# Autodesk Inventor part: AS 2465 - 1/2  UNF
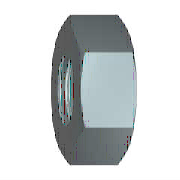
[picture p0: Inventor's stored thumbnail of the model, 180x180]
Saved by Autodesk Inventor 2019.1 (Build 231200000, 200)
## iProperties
IsCustomPart: 0
Created: 2018-01
Part Number: AS 2465 - 1/2  UNF
Material: Steel, Mild
Description: Unified hexagon bolts, screws and nuts (UNC and UNF threads)
Document SubType Name: Modeling
Standard: AS 2465
Designer: Justin
Standards Organization: AS
Language: en-US
Size Designation: 1/2  UNF
Categories: <MemberInstance><Categories><Category DisplayName="Fasteners" InternalName="e4da775c-781d-43d5-af7c-5136215cf5a6" Mnemonic="FSTN"><Category DisplayName="Nuts" I
Density: 7.85 g/cm^3
Appearance: Semi-Polished
Mass: 18.8733 g
Surface Area: 15.332 cm^2
Volume: 2.40424 cm^3
Author: Justin
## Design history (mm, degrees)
sketch "Sketch1"
  geometry: L1 (-10.999, 0)-(-5.499, 9.525); L2 (-5.499, 9.525)-(5.499, 9.525); L3 (5.499, 9.525)-(10.999, 0); L4 (10.999, 0)-(5.499, -9.525); L5 (5.499, -9.525)-(-5.499, -9.525); L6 (-5.499, -9.525)-(-10.999, 0); 2 further points
  constraints: 12 end point, 1 coincident, 1 horizontal, 11 other
  dimensions: "d0" = 21.99705 distance of L3.end L1.start (= 1.1547 x SW)
extrude "Body" new body sketch "Sketch1" distance "d1" = 11.3792 (= KOH); taper "d2" = 0 deg
sketch "Sketch2"
  geometry: L1 (0, 5.499)-(0, 10.999) reference; L2 (0, 10.999)-(11.379, 10.999) reference; L3 (11.379, 5.499)-(11.379, 10.999) reference; L4 (-2.276, 0)-(13.655, 0) reference; L5 (0.851, 10.999)-(0, 9.525); L6 (10.528, 10.999)-(11.379, 9.525)
  constraints: 4 end point, 4 point on line
  dimensions: "d3" = 30 deg angle of L1 L5 (= ANG1); "d4" = 30 deg angle of L3 L6 (= ANG2); "d5" = 19.05 diameter of L5.end L4 (= SW0); "d6" = 19.05 diameter of L6.end L4 (= SW01)
revolve "Chamfer1" sketch "Sketch2" stored, may be unused: angle "d7" = 90 deg
sketch "Sketch3"
  geometry: A1 r 9.525 centre (0, 0) between (-4.762, -8.249) and (4.763, -8.249) reference; 1 further point
  constraints: 1 coincident
hole "Thread" sketch "Sketch3" at (0, 0) diameter "d25" = 11.3284; stored, may be unused: countersink angle "d29" = 82 deg, drill point angle "d31" = 118 deg; dims "d26" = 6, "d27" = 4, "d28" = 2, "d30" = 8
workaxis "Work Axis1"
workplane "Work Plane1"
body "Solid1"
chamfer "Chamfer2" distance "d8" = 0.68741 (= -0.5 x GD1 + 0.5 x NND); stored, may be unused: angle "d9" = 30 deg, second distance "d40" = 0.68741 (= -0.5 x GD1 + 0.5 x NND)
chamfer "Chamfer3" distance "d10" = 0.68741 (= -0.5 x GD1 + 0.5 x NND); stored, may be unused: angle "d11" = 30 deg, second distance "d41" = 0.68741 (= -0.5 x GD1 + 0.5 x NND)
other parameters: "ANG1" = 30 deg [user parameter; used in 1 equation term], "ANG2" = 30 deg [user parameter; used in 1 equation term], "NND" = 12.7 [user parameter; used in 4 equation terms], "KOH" = 11.3792 [user parameter; used in 1 equation term], "SW" = 19.05 [user parameter; used in 4 equation terms], "SW0" = 19.05 (= SW) [user parameter; used in 1 equation term], "SW01" = 19.05 (= SW) [user parameter; used in 1 equation term], "GD1" = 11.32518 (computed from THREADDIA, PTC, TOA) [user parameter; used in 4 equation terms], "d13" = 0, "d14" = 0, "d39" = 0, "d42" = 0, "THREADDIA" = 12.7 [user parameter; used in 1 equation term], "TOA" = 30 deg [user parameter; used in 1 equation term], "PTC" = 1.27 (computed from TPU) [user parameter; used in 1 equation term], "E0" = 22.00275 (= 1.155 x SW) [user parameter]
